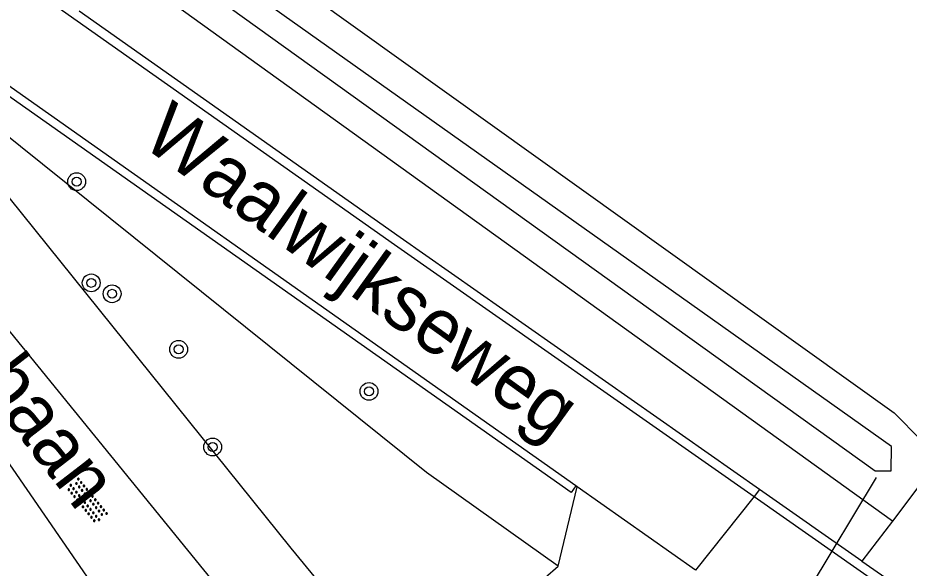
# Model space of a CAD drawing. Extents: x 136000 to 141000, y 400494 to 402006.
# Drawn here: x 136611.8 to 136651.8, y 401355.34 to 401380.05 of the extents above; entities that cross this region are included whole.
import ezdxf

# ---------------------------------------------------------------- set-up
doc = ezdxf.new("R2010")
doc.units = 0
for name, color, linetype in [('gg-anno-openbare ruimte label', 7, 'Continuous'), ('gg-knt-onverhard', 7, 'Continuous'), ('gg-knt-verharding', 7, 'Continuous'), ('gg-kntw-bovenkant insteek waterloop', 7, 'Continuous'), ('gg-kntw-waterlijn', 7, 'Continuous'), ('gg-kwrk-duiker nz buis', 7, 'Continuous'), ('gt-grn-groengrens', 7, 'Continuous'), ('gt-grn-weggrens', 7, 'Continuous'), ('gt-symb-boom', 7, 'Continuous'), ('gt-symb-overige verharding', 7, 'Continuous')]:
    doc.layers.add(name, color=color, linetype=linetype)

# ---------------------------------------------------------------- blocks, each defined once
blk = doc.blocks.new('gt0-BOOM')
at = {"layer": 'gt-symb-boom'}
for radius in [0.4, 0.2]:
    blk.add_circle((0, 0), radius, dxfattribs=at)
blk = doc.blocks.new('gt0-OVH')
at = {"layer": 'gt-symb-overige verharding'}
for points in [[(-0.972, 0.298), (-0.967, 0.308), (-0.965, 0.319), (-0.966, 0.33), (-0.971, 0.34), (-0.978, 0.348), (-0.988, 0.353), (-0.999, 0.355), (-1.01, 0.354), (-1.02, 0.349), (-1.028, 0.342), (-1.033, 0.332), (-1.035, 0.321), (-1.034, 0.31), (-1.029, 0.3), (-1.022, 0.292), (-1.012, 0.287), (-1.001, 0.285), (-0.99, 0.286), (-0.98, 0.291)], [(-0.872, 0.106), (-0.867, 0.116), (-0.865, 0.126), (-0.866, 0.137), (-0.871, 0.147), (-0.878, 0.156), (-0.888, 0.161), (-0.899, 0.163), (-0.91, 0.162), (-0.92, 0.157), (-0.928, 0.15), (-0.933, 0.14), (-0.935, 0.129), (-0.934, 0.118), (-0.929, 0.108), (-0.922, 0.1), (-0.912, 0.095), (-0.901, 0.092), (-0.89, 0.094), (-0.88, 0.098)], [(-0.772, 0.298), (-0.767, 0.308), (-0.765, 0.319), (-0.766, 0.33), (-0.771, 0.34), (-0.778, 0.348), (-0.788, 0.353), (-0.799, 0.355), (-0.81, 0.354), (-0.82, 0.349), (-0.828, 0.342), (-0.833, 0.332), (-0.835, 0.321), (-0.834, 0.31), (-0.829, 0.3), (-0.822, 0.292), (-0.812, 0.287), (-0.801, 0.285), (-0.79, 0.286), (-0.78, 0.291)], [(-0.672, 0.106), (-0.667, 0.116), (-0.665, 0.126), (-0.666, 0.137), (-0.671, 0.147), (-0.678, 0.156), (-0.688, 0.161), (-0.699, 0.163), (-0.71, 0.162), (-0.72, 0.157), (-0.728, 0.15), (-0.733, 0.14), (-0.735, 0.129), (-0.734, 0.118), (-0.729, 0.108), (-0.722, 0.1), (-0.712, 0.095), (-0.701, 0.092), (-0.69, 0.094), (-0.68, 0.098)], [(-0.572, 0.298), (-0.567, 0.308), (-0.565, 0.319), (-0.566, 0.33), (-0.571, 0.34), (-0.578, 0.348), (-0.588, 0.353), (-0.599, 0.355), (-0.61, 0.354), (-0.62, 0.349), (-0.628, 0.342), (-0.633, 0.332), (-0.635, 0.321), (-0.634, 0.31), (-0.629, 0.3), (-0.622, 0.292), (-0.612, 0.287), (-0.601, 0.285), (-0.59, 0.286), (-0.58, 0.291)], [(-0.472, 0.106), (-0.467, 0.116), (-0.465, 0.126), (-0.466, 0.137), (-0.471, 0.147), (-0.478, 0.156), (-0.488, 0.161), (-0.499, 0.163), (-0.51, 0.162), (-0.52, 0.157), (-0.528, 0.15), (-0.533, 0.14), (-0.535, 0.129), (-0.534, 0.118), (-0.529, 0.108), (-0.522, 0.1), (-0.512, 0.095), (-0.501, 0.092), (-0.49, 0.094), (-0.48, 0.098)], [(-0.372, 0.298), (-0.367, 0.308), (-0.365, 0.319), (-0.366, 0.33), (-0.371, 0.34), (-0.378, 0.348), (-0.388, 0.353), (-0.399, 0.355), (-0.41, 0.354), (-0.42, 0.349), (-0.428, 0.342), (-0.433, 0.332), (-0.435, 0.321), (-0.434, 0.31), (-0.429, 0.3), (-0.422, 0.292), (-0.412, 0.287), (-0.401, 0.285), (-0.39, 0.286), (-0.38, 0.291)], [(-0.272, 0.106), (-0.267, 0.116), (-0.265, 0.126), (-0.266, 0.137), (-0.271, 0.147), (-0.278, 0.156), (-0.288, 0.161), (-0.299, 0.163), (-0.31, 0.162), (-0.32, 0.157), (-0.328, 0.15), (-0.333, 0.14), (-0.335, 0.129), (-0.334, 0.118), (-0.329, 0.108), (-0.322, 0.1), (-0.312, 0.095), (-0.301, 0.092), (-0.29, 0.094), (-0.28, 0.098)], [(-0.172, 0.298), (-0.167, 0.308), (-0.165, 0.319), (-0.166, 0.33), (-0.171, 0.34), (-0.178, 0.348), (-0.188, 0.353), (-0.199, 0.355), (-0.21, 0.354), (-0.22, 0.349), (-0.228, 0.342), (-0.233, 0.332), (-0.235, 0.321), (-0.234, 0.31), (-0.229, 0.3), (-0.222, 0.292), (-0.212, 0.287), (-0.201, 0.285), (-0.19, 0.286), (-0.18, 0.291)], [(-0.072, 0.106), (-0.067, 0.116), (-0.065, 0.126), (-0.066, 0.137), (-0.071, 0.147), (-0.078, 0.156), (-0.088, 0.161), (-0.099, 0.163), (-0.11, 0.162), (-0.12, 0.157), (-0.128, 0.15), (-0.133, 0.14), (-0.135, 0.129), (-0.134, 0.118), (-0.129, 0.108), (-0.122, 0.1), (-0.112, 0.095), (-0.101, 0.092), (-0.09, 0.094), (-0.08, 0.098)], [(0.028, 0.298), (0.033, 0.308), (0.035, 0.319), (0.034, 0.33), (0.029, 0.34), (0.022, 0.348), (0.012, 0.353), (0.001, 0.355), (-0.01, 0.354), (-0.02, 0.349), (-0.028, 0.342), (-0.033, 0.332), (-0.035, 0.321), (-0.034, 0.31), (-0.029, 0.3), (-0.022, 0.292), (-0.012, 0.287), (-0.001, 0.285), (0.01, 0.286), (0.02, 0.291)], [(0.128, 0.106), (0.133, 0.116), (0.135, 0.126), (0.134, 0.137), (0.129, 0.147), (0.122, 0.156), (0.112, 0.161), (0.101, 0.163), (0.09, 0.162), (0.08, 0.157), (0.072, 0.15), (0.067, 0.14), (0.065, 0.129), (0.066, 0.118), (0.071, 0.108), (0.078, 0.1), (0.088, 0.095), (0.099, 0.092), (0.11, 0.094), (0.12, 0.098)], [(0.228, 0.298), (0.233, 0.308), (0.235, 0.319), (0.234, 0.33), (0.229, 0.34), (0.222, 0.348), (0.212, 0.353), (0.201, 0.355), (0.19, 0.354), (0.18, 0.349), (0.172, 0.342), (0.167, 0.332), (0.165, 0.321), (0.166, 0.31), (0.171, 0.3), (0.178, 0.292), (0.188, 0.287), (0.199, 0.285), (0.21, 0.286), (0.22, 0.291)], [(0.328, 0.106), (0.333, 0.116), (0.335, 0.126), (0.334, 0.137), (0.329, 0.147), (0.322, 0.156), (0.312, 0.161), (0.301, 0.163), (0.29, 0.162), (0.28, 0.157), (0.272, 0.15), (0.267, 0.14), (0.265, 0.129), (0.266, 0.118), (0.271, 0.108), (0.278, 0.1), (0.288, 0.095), (0.299, 0.092), (0.31, 0.094), (0.32, 0.098)], [(0.428, 0.298), (0.433, 0.308), (0.435, 0.319), (0.434, 0.33), (0.429, 0.34), (0.422, 0.348), (0.412, 0.353), (0.401, 0.355), (0.39, 0.354), (0.38, 0.349), (0.372, 0.342), (0.367, 0.332), (0.365, 0.321), (0.366, 0.31), (0.371, 0.3), (0.378, 0.292), (0.388, 0.287), (0.399, 0.285), (0.41, 0.286), (0.42, 0.291)], [(0.528, 0.106), (0.533, 0.116), (0.535, 0.126), (0.534, 0.137), (0.529, 0.147), (0.522, 0.156), (0.512, 0.161), (0.501, 0.163), (0.49, 0.162), (0.48, 0.157), (0.472, 0.15), (0.467, 0.14), (0.465, 0.129), (0.466, 0.118), (0.471, 0.108), (0.478, 0.1), (0.488, 0.095), (0.499, 0.092), (0.51, 0.094), (0.52, 0.098)], [(0.628, 0.298), (0.633, 0.308), (0.635, 0.319), (0.634, 0.33), (0.629, 0.34), (0.622, 0.348), (0.612, 0.353), (0.601, 0.355), (0.59, 0.354), (0.58, 0.349), (0.572, 0.342), (0.567, 0.332), (0.565, 0.321), (0.566, 0.31), (0.571, 0.3), (0.578, 0.292), (0.588, 0.287), (0.599, 0.285), (0.61, 0.286), (0.62, 0.291)], [(0.728, 0.106), (0.733, 0.116), (0.735, 0.126), (0.734, 0.137), (0.729, 0.147), (0.722, 0.156), (0.712, 0.161), (0.701, 0.163), (0.69, 0.162), (0.68, 0.157), (0.672, 0.15), (0.667, 0.14), (0.665, 0.129), (0.666, 0.118), (0.671, 0.108), (0.678, 0.1), (0.688, 0.095), (0.699, 0.092), (0.71, 0.094), (0.72, 0.098)], [(0.828, 0.298), (0.833, 0.308), (0.835, 0.319), (0.834, 0.33), (0.829, 0.34), (0.822, 0.348), (0.812, 0.353), (0.801, 0.355), (0.79, 0.354), (0.78, 0.349), (0.772, 0.342), (0.767, 0.332), (0.765, 0.321), (0.766, 0.31), (0.771, 0.3), (0.778, 0.292), (0.788, 0.287), (0.799, 0.285), (0.81, 0.286), (0.82, 0.291)], [(0.928, 0.106), (0.933, 0.116), (0.935, 0.126), (0.934, 0.137), (0.929, 0.147), (0.922, 0.156), (0.912, 0.161), (0.901, 0.163), (0.89, 0.162), (0.88, 0.157), (0.872, 0.15), (0.867, 0.14), (0.865, 0.129), (0.866, 0.118), (0.871, 0.108), (0.878, 0.1), (0.888, 0.095), (0.899, 0.092), (0.91, 0.094), (0.92, 0.098)], [(1.028, 0.298), (1.033, 0.308), (1.035, 0.319), (1.034, 0.33), (1.029, 0.34), (1.022, 0.348), (1.012, 0.353), (1.001, 0.355), (0.99, 0.354), (0.98, 0.349), (0.972, 0.342), (0.967, 0.332), (0.965, 0.321), (0.966, 0.31), (0.971, 0.3), (0.978, 0.292), (0.988, 0.287), (0.999, 0.285), (1.01, 0.286), (1.02, 0.291)], [(-0.972, -0.142), (-0.967, -0.132), (-0.965, -0.121), (-0.966, -0.11), (-0.971, -0.1), (-0.978, -0.092), (-0.988, -0.087), (-0.999, -0.085), (-1.01, -0.086), (-1.02, -0.091), (-1.028, -0.098), (-1.033, -0.108), (-1.035, -0.119), (-1.034, -0.13), (-1.029, -0.14), (-1.022, -0.148), (-1.012, -0.153), (-1.001, -0.155), (-0.99, -0.154), (-0.98, -0.149)], [(-0.872, -0.334), (-0.867, -0.324), (-0.865, -0.314), (-0.866, -0.303), (-0.871, -0.293), (-0.878, -0.284), (-0.888, -0.279), (-0.899, -0.277), (-0.91, -0.278), (-0.92, -0.283), (-0.928, -0.29), (-0.933, -0.3), (-0.935, -0.311), (-0.934, -0.322), (-0.929, -0.332), (-0.922, -0.34), (-0.912, -0.345), (-0.901, -0.348), (-0.89, -0.346), (-0.88, -0.342)], [(-0.772, -0.142), (-0.767, -0.132), (-0.765, -0.121), (-0.766, -0.11), (-0.771, -0.1), (-0.778, -0.092), (-0.788, -0.087), (-0.799, -0.085), (-0.81, -0.086), (-0.82, -0.091), (-0.828, -0.098), (-0.833, -0.108), (-0.835, -0.119), (-0.834, -0.13), (-0.829, -0.14), (-0.822, -0.148), (-0.812, -0.153), (-0.801, -0.155), (-0.79, -0.154), (-0.78, -0.149)], [(-0.672, -0.334), (-0.667, -0.324), (-0.665, -0.314), (-0.666, -0.303), (-0.671, -0.293), (-0.678, -0.284), (-0.688, -0.279), (-0.699, -0.277), (-0.71, -0.278), (-0.72, -0.283), (-0.728, -0.29), (-0.733, -0.3), (-0.735, -0.311), (-0.734, -0.322), (-0.729, -0.332), (-0.722, -0.34), (-0.712, -0.345), (-0.701, -0.348), (-0.69, -0.346), (-0.68, -0.342)], [(-0.572, -0.142), (-0.567, -0.132), (-0.565, -0.121), (-0.566, -0.11), (-0.571, -0.1), (-0.578, -0.092), (-0.588, -0.087), (-0.599, -0.085), (-0.61, -0.086), (-0.62, -0.091), (-0.628, -0.098), (-0.633, -0.108), (-0.635, -0.119), (-0.634, -0.13), (-0.629, -0.14), (-0.622, -0.148), (-0.612, -0.153), (-0.601, -0.155), (-0.59, -0.154), (-0.58, -0.149)], [(-0.472, -0.334), (-0.467, -0.324), (-0.465, -0.314), (-0.466, -0.303), (-0.471, -0.293), (-0.478, -0.284), (-0.488, -0.279), (-0.499, -0.277), (-0.51, -0.278), (-0.52, -0.283), (-0.528, -0.29), (-0.533, -0.3), (-0.535, -0.311), (-0.534, -0.322), (-0.529, -0.332), (-0.522, -0.34), (-0.512, -0.345), (-0.501, -0.348), (-0.49, -0.346), (-0.48, -0.342)], [(-0.372, -0.142), (-0.367, -0.132), (-0.365, -0.121), (-0.366, -0.11), (-0.371, -0.1), (-0.378, -0.092), (-0.388, -0.087), (-0.399, -0.085), (-0.41, -0.086), (-0.42, -0.091), (-0.428, -0.098), (-0.433, -0.108), (-0.435, -0.119), (-0.434, -0.13), (-0.429, -0.14), (-0.422, -0.148), (-0.412, -0.153), (-0.401, -0.155), (-0.39, -0.154), (-0.38, -0.149)], [(-0.272, -0.334), (-0.267, -0.324), (-0.265, -0.314), (-0.266, -0.303), (-0.271, -0.293), (-0.278, -0.284), (-0.288, -0.279), (-0.299, -0.277), (-0.31, -0.278), (-0.32, -0.283), (-0.328, -0.29), (-0.333, -0.3), (-0.335, -0.311), (-0.334, -0.322), (-0.329, -0.332), (-0.322, -0.34), (-0.312, -0.345), (-0.301, -0.348), (-0.29, -0.346), (-0.28, -0.342)], [(-0.172, -0.142), (-0.167, -0.132), (-0.165, -0.121), (-0.166, -0.11), (-0.171, -0.1), (-0.178, -0.092), (-0.188, -0.087), (-0.199, -0.085), (-0.21, -0.086), (-0.22, -0.091), (-0.228, -0.098), (-0.233, -0.108), (-0.235, -0.119), (-0.234, -0.13), (-0.229, -0.14), (-0.222, -0.148), (-0.212, -0.153), (-0.201, -0.155), (-0.19, -0.154), (-0.18, -0.149)], [(-0.072, -0.334), (-0.067, -0.324), (-0.065, -0.314), (-0.066, -0.303), (-0.071, -0.293), (-0.078, -0.284), (-0.088, -0.279), (-0.099, -0.277), (-0.11, -0.278), (-0.12, -0.283), (-0.128, -0.29), (-0.133, -0.3), (-0.135, -0.311), (-0.134, -0.322), (-0.129, -0.332), (-0.122, -0.34), (-0.112, -0.345), (-0.101, -0.348), (-0.09, -0.346), (-0.08, -0.342)], [(0.028, -0.142), (0.033, -0.132), (0.035, -0.121), (0.034, -0.11), (0.029, -0.1), (0.022, -0.092), (0.012, -0.087), (0.001, -0.085), (-0.01, -0.086), (-0.02, -0.091), (-0.028, -0.098), (-0.033, -0.108), (-0.035, -0.119), (-0.034, -0.13), (-0.029, -0.14), (-0.022, -0.148), (-0.012, -0.153), (-0.001, -0.155), (0.01, -0.154), (0.02, -0.149)], [(0.128, -0.334), (0.133, -0.324), (0.135, -0.314), (0.134, -0.303), (0.129, -0.293), (0.122, -0.284), (0.112, -0.279), (0.101, -0.277), (0.09, -0.278), (0.08, -0.283), (0.072, -0.29), (0.067, -0.3), (0.065, -0.311), (0.066, -0.322), (0.071, -0.332), (0.078, -0.34), (0.088, -0.345), (0.099, -0.348), (0.11, -0.346), (0.12, -0.342)], [(0.228, -0.142), (0.233, -0.132), (0.235, -0.121), (0.234, -0.11), (0.229, -0.1), (0.222, -0.092), (0.212, -0.087), (0.201, -0.085), (0.19, -0.086), (0.18, -0.091), (0.172, -0.098), (0.167, -0.108), (0.165, -0.119), (0.166, -0.13), (0.171, -0.14), (0.178, -0.148), (0.188, -0.153), (0.199, -0.155), (0.21, -0.154), (0.22, -0.149)], [(0.328, -0.334), (0.333, -0.324), (0.335, -0.314), (0.334, -0.303), (0.329, -0.293), (0.322, -0.284), (0.312, -0.279), (0.301, -0.277), (0.29, -0.278), (0.28, -0.283), (0.272, -0.29), (0.267, -0.3), (0.265, -0.311), (0.266, -0.322), (0.271, -0.332), (0.278, -0.34), (0.288, -0.345), (0.299, -0.348), (0.31, -0.346), (0.32, -0.342)], [(0.428, -0.142), (0.433, -0.132), (0.435, -0.121), (0.434, -0.11), (0.429, -0.1), (0.422, -0.092), (0.412, -0.087), (0.401, -0.085), (0.39, -0.086), (0.38, -0.091), (0.372, -0.098), (0.367, -0.108), (0.365, -0.119), (0.366, -0.13), (0.371, -0.14), (0.378, -0.148), (0.388, -0.153), (0.399, -0.155), (0.41, -0.154), (0.42, -0.149)], [(0.528, -0.334), (0.533, -0.324), (0.535, -0.314), (0.534, -0.303), (0.529, -0.293), (0.522, -0.284), (0.512, -0.279), (0.501, -0.277), (0.49, -0.278), (0.48, -0.283), (0.472, -0.29), (0.467, -0.3), (0.465, -0.311), (0.466, -0.322), (0.471, -0.332), (0.478, -0.34), (0.488, -0.345), (0.499, -0.348), (0.51, -0.346), (0.52, -0.342)], [(0.628, -0.142), (0.633, -0.132), (0.635, -0.121), (0.634, -0.11), (0.629, -0.1), (0.622, -0.092), (0.612, -0.087), (0.601, -0.085), (0.59, -0.086), (0.58, -0.091), (0.572, -0.098), (0.567, -0.108), (0.565, -0.119), (0.566, -0.13), (0.571, -0.14), (0.578, -0.148), (0.588, -0.153), (0.599, -0.155), (0.61, -0.154), (0.62, -0.149)], [(0.728, -0.334), (0.733, -0.324), (0.735, -0.314), (0.734, -0.303), (0.729, -0.293), (0.722, -0.284), (0.712, -0.279), (0.701, -0.277), (0.69, -0.278), (0.68, -0.283), (0.672, -0.29), (0.667, -0.3), (0.665, -0.311), (0.666, -0.322), (0.671, -0.332), (0.678, -0.34), (0.688, -0.345), (0.699, -0.348), (0.71, -0.346), (0.72, -0.342)], [(0.828, -0.142), (0.833, -0.132), (0.835, -0.121), (0.834, -0.11), (0.829, -0.1), (0.822, -0.092), (0.812, -0.087), (0.801, -0.085), (0.79, -0.086), (0.78, -0.091), (0.772, -0.098), (0.767, -0.108), (0.765, -0.119), (0.766, -0.13), (0.771, -0.14), (0.778, -0.148), (0.788, -0.153), (0.799, -0.155), (0.81, -0.154), (0.82, -0.149)], [(0.928, -0.334), (0.933, -0.324), (0.935, -0.314), (0.934, -0.303), (0.929, -0.293), (0.922, -0.284), (0.912, -0.279), (0.901, -0.277), (0.89, -0.278), (0.88, -0.283), (0.872, -0.29), (0.867, -0.3), (0.865, -0.311), (0.866, -0.322), (0.871, -0.332), (0.878, -0.34), (0.888, -0.345), (0.899, -0.348), (0.91, -0.346), (0.92, -0.342)], [(1.028, -0.142), (1.033, -0.132), (1.035, -0.121), (1.034, -0.11), (1.029, -0.1), (1.022, -0.092), (1.012, -0.087), (1.001, -0.085), (0.99, -0.086), (0.98, -0.091), (0.972, -0.098), (0.967, -0.108), (0.965, -0.119), (0.966, -0.13), (0.971, -0.14), (0.978, -0.148), (0.988, -0.153), (0.999, -0.155), (1.01, -0.154), (1.02, -0.149)]]:
    blk.add_lwpolyline(points, close=True, dxfattribs=at)

msp = doc.modelspace()

# ---------------------------------------------------------------- linework, layer by layer
at = {"layer": 'gg-knt-onverhard'}
for points in [[(136623.421, 401344.422), (136616.638, 401352.428), (136609.359, 401363.009), (136604.239, 401369.07), (136597.798, 401377.88), (136596.84, 401379.759)], [(136604.477, 401376.169), (136604.649, 401375.73), (136606.868, 401371.55), (136621.037, 401354.137), (136626.737, 401347.313)]]:
    msp.add_lwpolyline(points, dxfattribs=at)
at = {"layer": 'gg-knt-verharding'}
for p, q in [((136652.889, 401359.903), (136651.056, 401357.454)), ((136636.811, 401358.614), (136636.901, 401358.993)), ((136636.901, 401358.993), (136636.839, 401359.037)), ((136642.206, 401355.249), (136636.901, 401358.993)), ((136649.68, 401355.652), (136645.087, 401358.874)), ((136636.042, 401355.425), (136636.811, 401358.614)), ((136644.838, 401358.561), (136651.207, 401354.098)), ((136651.056, 401357.454), (136649.68, 401355.652)), ((136649.68, 401355.652), (136651.435, 401354.421)), ((136629.454, 401349.681), (136636.042, 401355.425))]:
    msp.add_line(p, q, dxfattribs=at)
for points in [[(136594.974, 401393.66), (136628.702, 401369.868), (136644.838, 401358.561)], [(136636.839, 401359.037), (136605.185, 401381.378), (136603.181, 401382.697)], [(136645.087, 401358.874), (136628.956, 401370.189), (136614.546, 401380.346)], [(136636.839, 401359.037), (136636.627, 401358.731), (136607.424, 401379.315)]]:
    msp.add_lwpolyline(points, dxfattribs=at)
at = {"layer": 'gg-kntw-bovenkant insteek waterloop'}
msp.add_line((136651.056, 401357.454), (136615.535, 401383.022), dxfattribs=at)
msp.add_lwpolyline([(136622.96, 401382.486), (136651.125, 401362.318), (136652.333, 401361.081), (136652.889, 401359.903)], dxfattribs=at)
at = {"layer": 'gg-kntw-waterlijn'}
msp.add_lwpolyline([(136617.086, 401383.549), (136644.984, 401363.506), (136650.268, 401359.711), (136650.993, 401359.702), (136651.006, 401360.796), (136641.575, 401367.491), (136623.284, 401380.474), (136617.756, 401384.482)], dxfattribs=at)
at = {"layer": 'gg-kwrk-duiker nz buis'}
msp.add_line((136643.484, 401348.02), (136650.332, 401359.414), dxfattribs=at)
at = {"layer": 'gt-grn-groengrens'}
for points in [[(136629.454, 401349.681), (136624.07, 401356.23), (136605.682, 401379.087)], [(136636.042, 401355.425), (136630.13, 401359.64), (136605.822, 401379.159)]]:
    msp.add_lwpolyline(points, dxfattribs=at)
at = {"layer": 'gt-grn-weggrens'}
for p, q in [((136645.087, 401358.874), (136644.838, 401358.561)), ((136644.838, 401358.561), (136642.206, 401355.249))]:
    msp.add_line(p, q, dxfattribs=at)

# ---------------------------------------------------------------- block references
at = {"layer": 'gt-symb-boom'}
for p in [(136614.435, 401372.693), (136615.09, 401368.149), (136616.027, 401367.66), (136619.012, 401365.165), (136627.557, 401363.276), (136620.539, 401360.778)]:
    msp.add_blockref('gt0-BOOM', p, dxfattribs=at)
at = {"layer": 'gt-symb-overige verharding', "rotation": -50.678359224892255}
msp.add_blockref('gt0-OVH', (136614.897, 401358.363), dxfattribs=at)

# ---------------------------------------------------------------- texts
at = {"layer": 'gg-anno-openbare ruimte label'}
for s, rotation, p in [('Waalwijksebaan', 307.6, (136599.752, 401376.96)), ('Waalwijkseweg', 324.3, (136617.259, 401374.378))]:
    msp.add_text(s, height=2.5, rotation=rotation, dxfattribs=at).set_placement(p)

doc.saveas('drawing.dxf')
